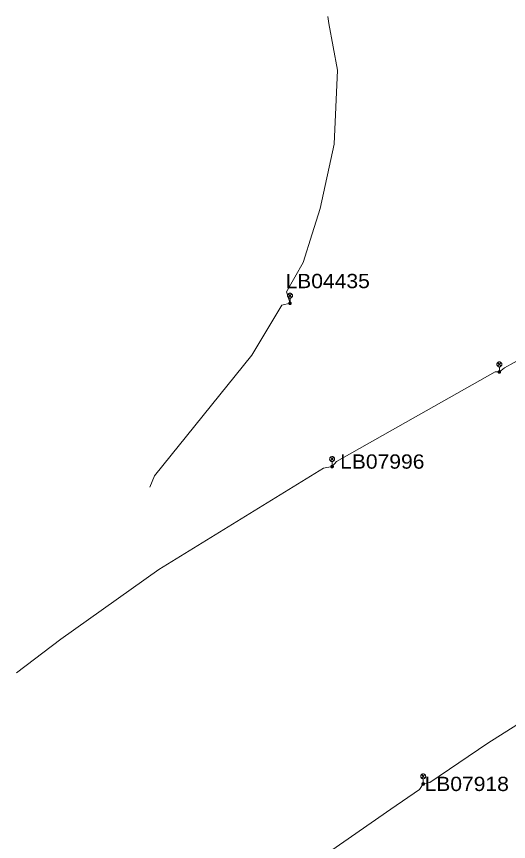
# Model space of a CAD drawing. Extents: x -688049 to -687261, y -973611 to -973038.
# Drawn here: x -688048.8 to -687974.3, y -973164.2 to -973039.2 of the extents above; entities that cross this region are included whole.
import ezdxf

# ---------------------------------------------------------------- set-up
doc = ezdxf.new("R2010")
doc.units = 0
doc.header["$LTSCALE"] = 0.87
doc.layers.add('1', color=7, linetype='Continuous', lineweight=13)

msp = doc.modelspace()

# ---------------------------------------------------------------- linework, layer by layer
at = {"layer": '1'}
for p, q in [((-688007.635, -973081.195), (-688007.105, -973081.725)), ((-688007.635, -973081.725), (-688007.105, -973081.195)), ((-688007.37, -973082.61), (-688007.37, -973081.835)), ((-687975.945, -973091.605), (-687975.415, -973092.135)), ((-687975.945, -973092.135), (-687975.415, -973091.605)), ((-687975.68, -973093.02), (-687975.68, -973092.245)), ((-688001.265, -973105.945), (-688000.735, -973106.475)), ((-688001.265, -973106.475), (-688000.735, -973105.945)), ((-688001, -973107.36), (-688001, -973106.585)), ((-687987.475, -973154.025), (-687986.945, -973154.555)), ((-687987.475, -973154.555), (-687986.945, -973154.025)), ((-687987.21, -973155.44), (-687987.21, -973154.665))]:
    msp.add_line(p, q, dxfattribs=at)
for points in [[(-688001.66, -973039.16), (-688001.488, -973040.203), (-688000.181, -973047.299), (-688000.681, -973058.493), (-688002.798, -973068.232), (-688004.021, -973072.107), (-688005.381, -973076.418), (-688007.881, -973080.898), (-688007.37, -973082.61)], [(-687949.39, -973080.1), (-687950.072, -973080.165), (-687969.061, -973089.148), (-687974.93, -973092.414), (-687975.68, -973093.02)], [(-688007.37, -973082.61), (-688008.588, -973082.883), (-688013.174, -973090.45), (-688027.881, -973108.768), (-688028.57, -973110.47)], [(-687975.68, -973093.02), (-687976.323, -973093.02), (-688000.333, -973106.603), (-688001, -973107.36)], [(-688048.77, -973138.6), (-688042.053, -973133.502), (-688027.219, -973122.955), (-688002.307, -973107.575), (-688001, -973107.36)], [(-687960.77, -973138.43), (-687961.54, -973139.222), (-687977.425, -973149.251), (-687986.227, -973155.219), (-687987.21, -973155.44)], [(-688013.43, -973174.08), (-688012.55, -973173.78), (-688009.306, -973171.228), (-687992.088, -973159.287), (-687987.773, -973156.273), (-687987.21, -973155.44)]]:
    msp.add_lwpolyline(points, dxfattribs=at)
for points in [[(-688006.995, -973081.46), (-688007.001, -973081.395), (-688007.018, -973081.332), (-688007.045, -973081.272), (-688007.083, -973081.219), (-688007.129, -973081.173), (-688007.182, -973081.135), (-688007.242, -973081.108), (-688007.305, -973081.091), (-688007.37, -973081.085), (-688007.435, -973081.091), (-688007.498, -973081.108), (-688007.558, -973081.135), (-688007.611, -973081.173), (-688007.657, -973081.219), (-688007.695, -973081.272), (-688007.722, -973081.332), (-688007.739, -973081.395), (-688007.745, -973081.46), (-688007.739, -973081.525), (-688007.722, -973081.588), (-688007.695, -973081.648), (-688007.657, -973081.701), (-688007.611, -973081.747), (-688007.558, -973081.785), (-688007.498, -973081.812), (-688007.435, -973081.829), (-688007.37, -973081.835), (-688007.305, -973081.829), (-688007.242, -973081.812), (-688007.182, -973081.785), (-688007.129, -973081.747), (-688007.083, -973081.701), (-688007.045, -973081.648), (-688007.018, -973081.588), (-688007.001, -973081.525)], [(-688007.18, -973082.61), (-688007.183, -973082.577), (-688007.191, -973082.545), (-688007.205, -973082.515), (-688007.224, -973082.488), (-688007.248, -973082.464), (-688007.275, -973082.445), (-688007.305, -973082.431), (-688007.337, -973082.423), (-688007.37, -973082.42), (-688007.403, -973082.423), (-688007.435, -973082.431), (-688007.465, -973082.445), (-688007.492, -973082.464), (-688007.516, -973082.488), (-688007.535, -973082.515), (-688007.549, -973082.545), (-688007.557, -973082.577), (-688007.56, -973082.61), (-688007.557, -973082.643), (-688007.549, -973082.675), (-688007.535, -973082.705), (-688007.516, -973082.732), (-688007.492, -973082.756), (-688007.465, -973082.775), (-688007.435, -973082.789), (-688007.403, -973082.797), (-688007.37, -973082.8), (-688007.337, -973082.797), (-688007.305, -973082.789), (-688007.275, -973082.775), (-688007.248, -973082.756), (-688007.224, -973082.732), (-688007.205, -973082.705), (-688007.191, -973082.675), (-688007.183, -973082.643)], [(-688007.32, -973082.61), (-688007.321, -973082.601), (-688007.323, -973082.593), (-688007.327, -973082.585), (-688007.332, -973082.578), (-688007.338, -973082.572), (-688007.345, -973082.567), (-688007.353, -973082.563), (-688007.361, -973082.561), (-688007.37, -973082.56), (-688007.379, -973082.561), (-688007.387, -973082.563), (-688007.395, -973082.567), (-688007.402, -973082.572), (-688007.408, -973082.578), (-688007.413, -973082.585), (-688007.417, -973082.593), (-688007.419, -973082.601), (-688007.42, -973082.61), (-688007.419, -973082.619), (-688007.417, -973082.627), (-688007.413, -973082.635), (-688007.408, -973082.642), (-688007.402, -973082.648), (-688007.395, -973082.653), (-688007.387, -973082.657), (-688007.379, -973082.659), (-688007.37, -973082.66), (-688007.361, -973082.659), (-688007.353, -973082.657), (-688007.345, -973082.653), (-688007.338, -973082.648), (-688007.332, -973082.642), (-688007.327, -973082.635), (-688007.323, -973082.627), (-688007.321, -973082.619)], [(-687975.305, -973091.87), (-687975.311, -973091.805), (-687975.328, -973091.742), (-687975.355, -973091.682), (-687975.393, -973091.629), (-687975.439, -973091.583), (-687975.492, -973091.545), (-687975.552, -973091.518), (-687975.615, -973091.501), (-687975.68, -973091.495), (-687975.745, -973091.501), (-687975.808, -973091.518), (-687975.868, -973091.545), (-687975.921, -973091.583), (-687975.967, -973091.629), (-687976.005, -973091.682), (-687976.032, -973091.742), (-687976.049, -973091.805), (-687976.055, -973091.87), (-687976.049, -973091.935), (-687976.032, -973091.998), (-687976.005, -973092.058), (-687975.967, -973092.111), (-687975.921, -973092.157), (-687975.868, -973092.195), (-687975.808, -973092.222), (-687975.745, -973092.239), (-687975.68, -973092.245), (-687975.615, -973092.239), (-687975.552, -973092.222), (-687975.492, -973092.195), (-687975.439, -973092.157), (-687975.393, -973092.111), (-687975.355, -973092.058), (-687975.328, -973091.998), (-687975.311, -973091.935)], [(-687975.49, -973093.02), (-687975.493, -973092.987), (-687975.501, -973092.955), (-687975.515, -973092.925), (-687975.534, -973092.898), (-687975.558, -973092.874), (-687975.585, -973092.855), (-687975.615, -973092.841), (-687975.647, -973092.833), (-687975.68, -973092.83), (-687975.713, -973092.833), (-687975.745, -973092.841), (-687975.775, -973092.855), (-687975.802, -973092.874), (-687975.826, -973092.898), (-687975.845, -973092.925), (-687975.859, -973092.955), (-687975.867, -973092.987), (-687975.87, -973093.02), (-687975.867, -973093.053), (-687975.859, -973093.085), (-687975.845, -973093.115), (-687975.826, -973093.142), (-687975.802, -973093.166), (-687975.775, -973093.185), (-687975.745, -973093.199), (-687975.713, -973093.207), (-687975.68, -973093.21), (-687975.647, -973093.207), (-687975.615, -973093.199), (-687975.585, -973093.185), (-687975.558, -973093.166), (-687975.534, -973093.142), (-687975.515, -973093.115), (-687975.501, -973093.085), (-687975.493, -973093.053)], [(-687975.63, -973093.02), (-687975.631, -973093.011), (-687975.633, -973093.003), (-687975.637, -973092.995), (-687975.642, -973092.988), (-687975.648, -973092.982), (-687975.655, -973092.977), (-687975.663, -973092.973), (-687975.671, -973092.971), (-687975.68, -973092.97), (-687975.689, -973092.971), (-687975.697, -973092.973), (-687975.705, -973092.977), (-687975.712, -973092.982), (-687975.718, -973092.988), (-687975.723, -973092.995), (-687975.727, -973093.003), (-687975.729, -973093.011), (-687975.73, -973093.02), (-687975.729, -973093.029), (-687975.727, -973093.037), (-687975.723, -973093.045), (-687975.718, -973093.052), (-687975.712, -973093.058), (-687975.705, -973093.063), (-687975.697, -973093.067), (-687975.689, -973093.069), (-687975.68, -973093.07), (-687975.671, -973093.069), (-687975.663, -973093.067), (-687975.655, -973093.063), (-687975.648, -973093.058), (-687975.642, -973093.052), (-687975.637, -973093.045), (-687975.633, -973093.037), (-687975.631, -973093.029)], [(-688000.625, -973106.21), (-688000.631, -973106.145), (-688000.648, -973106.082), (-688000.675, -973106.022), (-688000.713, -973105.969), (-688000.759, -973105.923), (-688000.812, -973105.885), (-688000.872, -973105.858), (-688000.935, -973105.841), (-688001, -973105.835), (-688001.065, -973105.841), (-688001.128, -973105.858), (-688001.188, -973105.885), (-688001.241, -973105.923), (-688001.287, -973105.969), (-688001.325, -973106.022), (-688001.352, -973106.082), (-688001.369, -973106.145), (-688001.375, -973106.21), (-688001.369, -973106.275), (-688001.352, -973106.338), (-688001.325, -973106.398), (-688001.287, -973106.451), (-688001.241, -973106.497), (-688001.188, -973106.535), (-688001.128, -973106.562), (-688001.065, -973106.579), (-688001, -973106.585), (-688000.935, -973106.579), (-688000.872, -973106.562), (-688000.812, -973106.535), (-688000.759, -973106.497), (-688000.713, -973106.451), (-688000.675, -973106.398), (-688000.648, -973106.338), (-688000.631, -973106.275)], [(-688000.81, -973107.36), (-688000.813, -973107.327), (-688000.821, -973107.295), (-688000.835, -973107.265), (-688000.854, -973107.238), (-688000.878, -973107.214), (-688000.905, -973107.195), (-688000.935, -973107.181), (-688000.967, -973107.173), (-688001, -973107.17), (-688001.033, -973107.173), (-688001.065, -973107.181), (-688001.095, -973107.195), (-688001.122, -973107.214), (-688001.146, -973107.238), (-688001.165, -973107.265), (-688001.179, -973107.295), (-688001.187, -973107.327), (-688001.19, -973107.36), (-688001.187, -973107.393), (-688001.179, -973107.425), (-688001.165, -973107.455), (-688001.146, -973107.482), (-688001.122, -973107.506), (-688001.095, -973107.525), (-688001.065, -973107.539), (-688001.033, -973107.547), (-688001, -973107.55), (-688000.967, -973107.547), (-688000.935, -973107.539), (-688000.905, -973107.525), (-688000.878, -973107.506), (-688000.854, -973107.482), (-688000.835, -973107.455), (-688000.821, -973107.425), (-688000.813, -973107.393)], [(-688000.95, -973107.36), (-688000.951, -973107.351), (-688000.953, -973107.343), (-688000.957, -973107.335), (-688000.962, -973107.328), (-688000.968, -973107.322), (-688000.975, -973107.317), (-688000.983, -973107.313), (-688000.991, -973107.311), (-688001, -973107.31), (-688001.009, -973107.311), (-688001.017, -973107.313), (-688001.025, -973107.317), (-688001.032, -973107.322), (-688001.038, -973107.328), (-688001.043, -973107.335), (-688001.047, -973107.343), (-688001.049, -973107.351), (-688001.05, -973107.36), (-688001.049, -973107.369), (-688001.047, -973107.377), (-688001.043, -973107.385), (-688001.038, -973107.392), (-688001.032, -973107.398), (-688001.025, -973107.403), (-688001.017, -973107.407), (-688001.009, -973107.409), (-688001, -973107.41), (-688000.991, -973107.409), (-688000.983, -973107.407), (-688000.975, -973107.403), (-688000.968, -973107.398), (-688000.962, -973107.392), (-688000.957, -973107.385), (-688000.953, -973107.377), (-688000.951, -973107.369)], [(-687986.835, -973154.29), (-687986.841, -973154.225), (-687986.858, -973154.162), (-687986.885, -973154.102), (-687986.923, -973154.049), (-687986.969, -973154.003), (-687987.022, -973153.965), (-687987.082, -973153.938), (-687987.145, -973153.921), (-687987.21, -973153.915), (-687987.275, -973153.921), (-687987.338, -973153.938), (-687987.398, -973153.965), (-687987.451, -973154.003), (-687987.497, -973154.049), (-687987.535, -973154.102), (-687987.562, -973154.162), (-687987.579, -973154.225), (-687987.585, -973154.29), (-687987.579, -973154.355), (-687987.562, -973154.418), (-687987.535, -973154.477), (-687987.497, -973154.531), (-687987.451, -973154.577), (-687987.398, -973154.615), (-687987.338, -973154.642), (-687987.275, -973154.659), (-687987.21, -973154.665), (-687987.145, -973154.659), (-687987.082, -973154.642), (-687987.022, -973154.615), (-687986.969, -973154.577), (-687986.923, -973154.531), (-687986.885, -973154.477), (-687986.858, -973154.418), (-687986.841, -973154.355)], [(-687987.02, -973155.44), (-687987.023, -973155.407), (-687987.031, -973155.375), (-687987.045, -973155.345), (-687987.064, -973155.318), (-687987.088, -973155.294), (-687987.115, -973155.275), (-687987.145, -973155.261), (-687987.177, -973155.253), (-687987.21, -973155.25), (-687987.243, -973155.253), (-687987.275, -973155.261), (-687987.305, -973155.275), (-687987.332, -973155.294), (-687987.356, -973155.318), (-687987.375, -973155.345), (-687987.389, -973155.375), (-687987.397, -973155.407), (-687987.4, -973155.44), (-687987.397, -973155.473), (-687987.389, -973155.505), (-687987.375, -973155.535), (-687987.356, -973155.562), (-687987.332, -973155.586), (-687987.305, -973155.605), (-687987.275, -973155.619), (-687987.243, -973155.627), (-687987.21, -973155.63), (-687987.177, -973155.627), (-687987.145, -973155.619), (-687987.115, -973155.605), (-687987.088, -973155.586), (-687987.064, -973155.562), (-687987.045, -973155.535), (-687987.031, -973155.505), (-687987.023, -973155.473)], [(-687987.16, -973155.44), (-687987.161, -973155.431), (-687987.163, -973155.423), (-687987.167, -973155.415), (-687987.172, -973155.408), (-687987.178, -973155.402), (-687987.185, -973155.397), (-687987.193, -973155.393), (-687987.201, -973155.391), (-687987.21, -973155.39), (-687987.219, -973155.391), (-687987.227, -973155.393), (-687987.235, -973155.397), (-687987.242, -973155.402), (-687987.248, -973155.408), (-687987.253, -973155.415), (-687987.257, -973155.423), (-687987.259, -973155.431), (-687987.26, -973155.44), (-687987.259, -973155.449), (-687987.257, -973155.457), (-687987.253, -973155.465), (-687987.248, -973155.472), (-687987.242, -973155.478), (-687987.235, -973155.483), (-687987.227, -973155.487), (-687987.219, -973155.489), (-687987.21, -973155.49), (-687987.201, -973155.489), (-687987.193, -973155.487), (-687987.185, -973155.483), (-687987.178, -973155.478), (-687987.172, -973155.472), (-687987.167, -973155.465), (-687987.163, -973155.457), (-687987.161, -973155.449)]]:
    msp.add_lwpolyline(points, close=True, dxfattribs=at)

# ---------------------------------------------------------------- texts
at = {"layer": '1', "width": 1.1}
for s, p in [('LB04435', (-688008.054, -973080.323)), ('LB07996', (-687999.789, -973107.677)), ('LB07918', (-687987.009, -973156.517))]:
    msp.add_text(s, height=2.167, dxfattribs=at).set_placement(p)

doc.saveas('drawing.dxf')
